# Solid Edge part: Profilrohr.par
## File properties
Last saved by: bmolnar
Revision: 79
Dokumentum tartalom típus: 0
Sűrűség: 0,000 kg/m^3
Pontosság: 0,990
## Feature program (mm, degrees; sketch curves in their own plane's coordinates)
base feature "unnamed BaseFeature 1"
thread "unnamed Thread 1"
thread "Menet_2"  ThreadDepth = 3.9 mm
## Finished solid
Body 1: solid body, 75 faces, 162 edges, 101 vertices.
  Faces by surface: plane 37, cylinder 24, cone 11, torus 3
  Edges by curve: line 77, circle 62, curve on surface 12, spline 7, ellipse 3, intersection 1
Bounding box of the edges (mm; curved faces can reach further): 25.000 x 25.000 x 32.000, from (-12.5, -12.5, 0) to (12.5, 12.5, 32).
Cylindrical faces by radius (mm): R0.5 x2, R1.5 x1, R1.8 x6, R1.9 x2, R2.067 x4, R2.8 x4, R6 x2, R6.85 x1, R6.95 x1, R7.3 x1
Conical faces (half-angle, radius in mm at the cone's reference point): 30 deg R6.225 x1, 30 deg R6.9943 x1, 30 deg R7.0943 x1, 45 deg R1.95 x4, 45 deg R2.217 x2, 45 deg R4.45 x1, 60 deg R0.25 x1
Toroidal faces (ring radius, tube radius in mm): R5 r1 x1, R7.2 r0.1 x2
Planar faces by outward normal: +x 3, +y 7, +z 8, -x 3, -y 6, -z 4, oblique 6
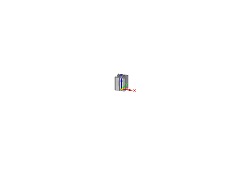
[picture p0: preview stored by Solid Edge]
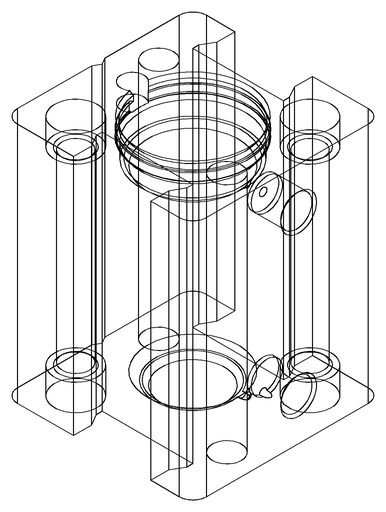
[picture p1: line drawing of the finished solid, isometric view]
